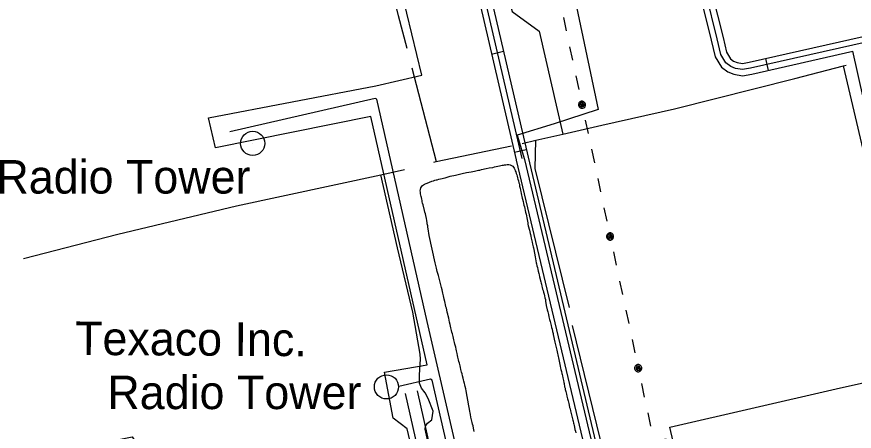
# Model space of a CAD drawing. Extents: x 3392644 to 3430565, y 576657 to 602123.
# Drawn here: x 3418875 to 3420949, y 586945 to 587973 of the extents above; entities that cross this region are included whole.
import ezdxf

# ---------------------------------------------------------------- set-up
doc = ezdxf.new("R2010")
doc.units = 0
for name, color, linetype in [('V-BLDG-IDEN', 7, 'Continuous'), ('V-ROAD-CNTR', 7, 'Continuous'), ('V-SITE-OTLN', 7, 'Continuous'), ('V-TOPO-SHOR', 7, 'Continuous'), ('V-TOPO-TOWR', 7, 'Continuous'), ('V-TOPO-TOWR-IDEN', 7, 'Continuous'), ('V-UTIL-LINE', 7, 'Continuous')]:
    doc.layers.add(name, color=color, linetype=linetype)

msp = doc.modelspace()

# ---------------------------------------------------------------- linework, layer by layer
at = {"layer": 'V-ROAD-CNTR'}
for p, q in [((3420080.7, 587886.6), (3420051.4, 587879.8)), ((3420729.6, 587869.3), (3420736.2, 587840)), ((3420137.2, 587643.1), (3420108, 587636.3))]:
    msp.add_line(p, q, dxfattribs=at)
for points in [[(3421051.4, 588862.7), (3421240.9, 588033.6), (3421246.2, 588012.9), (3421246.1, 588006.5), (3421241.1, 587991.7), (3421237.3, 587982.5), (3421228.4, 587972.9), (3421213.1, 587965.1), (3421166, 587952.4), (3420692.6, 587845.6), (3420672.4, 587842), (3420655.1, 587845.1), (3420643.4, 587849.4), (3420631.7, 587858.5), (3420619, 587879.5), (3420609.9, 587918.2), (3420582.3, 588029.6), (3420480, 588457.4), (3420453.1, 588526.7)], [(3420473.4, 588516), (3420494.4, 588461.9), (3420596.9, 588033.2), (3420624.5, 587921.8), (3420633, 587885.2), (3420643.1, 587868.7), (3420650.8, 587862.7), (3420659.1, 587859.6), (3420672.4, 587857.2), (3420689.6, 587860.3), (3421162.4, 587966.9), (3421207.7, 587979.2), (3421219.2, 587985.1), (3421224.5, 587990.7), (3421227, 587997), (3421231.1, 588009.1), (3421231.2, 588011.2), (3421226.4, 588030.1), (3421040, 588845.6)], [(3420443.8, 588509.3), (3420465.7, 588452.9), (3420567.8, 588026.1), (3420595.3, 587914.7), (3420604.9, 587873.7), (3420620.3, 587848.4), (3420636, 587836.1), (3420651.2, 587830.6), (3420672.4, 587826.7), (3420695.6, 587830.8), (3420945.6, 587887.3)], [(3420126.9, 587621.2), (3419969.1, 588300.7), (3419969, 588329.7), (3419970.4, 588348.5), (3419984.9, 588420.6)], [(3419965.6, 588400.8), (3419955.5, 588350.6), (3419954, 588330.2), (3419954.1, 588299), (3420112.3, 587617.8)], [(3419997.7, 588408.1), (3419985.3, 588346.5), (3419984, 588329.2), (3419984.1, 588302.5), (3420141.5, 587624.6)], [(3421114.8, 587130.3), (3420945.6, 587887.3)], [(3420141.5, 587624.6), (3420305.5, 586932.7), (3420314.8, 586891.6)], [(3420112.3, 587617.7), (3420276.3, 586925.9), (3420362.9, 586544), (3420374.6, 586499.3)], [(3419866.9, 587045.2), (3419967.6, 586597), (3419970.7, 586573.9), (3419960.1, 586554.5), (3419941.9, 586542.5), (3419922, 586537.6), (3419898.8, 586539.5), (3419878.4, 586544.6), (3419812.2, 586592)], [(3419837.6, 587038.6), (3419925, 586650.1)]]:
    msp.add_lwpolyline(points, dxfattribs=at)
at = {"layer": 'V-SITE-OTLN'}
for points in [[(3420198.5, 588296.2), (3420315.3, 587742.8), (3420206.2, 587707.1), (3420114.8, 587679.6), (3420133.1, 587619.1), (3420308.5, 586877.4), (3420348.3, 586694.8), (3420544.7, 586731.4), (3420492.6, 586955.3), (3420905, 587050.2), (3421093.6, 587092.6)], [(3418830.7, 586373.5), (3419131.5, 586431.4), (3419137.7, 586454.6), (3419125.3, 586527.4), (3419063.2, 586911.5), (3419161.3, 586931.7), (3419171.3, 586916.3), (3419172.8, 586898.4), (3419244.6, 586498.5), (3419674.8, 586581.6), (3419894.5, 586635.1), (3419902.8, 586662.5), (3419897.6, 586716.1), (3419842, 586951.5), (3419807.5, 586977.5), (3419785.8, 587091.7), (3419891.9, 587110), (3419751.8, 587726), (3419367.2, 587647.7), (3419349.9, 587722.2), (3419764.5, 587802.1), (3419878.1, 587827.9), (3419791.9, 588187.7)]]:
    msp.add_lwpolyline(points, dxfattribs=at)
at = {"layer": 'V-TOPO-SHOR'}
for p, q in [((3421096.6, 587108.6), (3420922.7, 587851)), ((3419853.7, 587846.4), (3419914.4, 587614.1))]:
    msp.add_line(p, q, dxfattribs=at)
for points in [[(3420058.1, 588398.7), (3420027.1, 588390), (3420020.8, 588380.5), (3420010.2, 588349.6), (3420061, 588146.3), (3420102, 587986.4), (3420168.9, 587937.5), (3420228.1, 587682.1)], [(3419792.8, 588085.1), (3419819.9, 587976.2), (3419841.1, 587894.9)], [(3420126.8, 587659.1), (3420161.1, 587666.9), (3420228.1, 587682.1), (3420324.1, 587703.8), (3420504.4, 587745), (3420801.9, 587819.7), (3420922.7, 587851), (3420929.5, 587852.8)], [(3420244.6, 587252.2), (3420158.9, 587597), (3420161.1, 587666.9)], [(3419908.1, 587612.8), (3419914.4, 587614.1), (3420100.4, 587653.3)], [(3419881.4, 587506.6), (3419880.5, 587510.5), (3419879.6, 587514.1), (3419879.1, 587517.4), (3419878.4, 587520.6), (3419877.3, 587524.5), (3419876.6, 587527.7), (3419876.3, 587530.9), (3419875.6, 587534.2), (3419874.8, 587537.9), (3419874.7, 587541.3), (3419875.1, 587544.9), (3419876.1, 587548.5), (3419877.7, 587551.2), (3419880.2, 587554.2), (3419882.6, 587556.1), (3419885.3, 587557.8), (3419889, 587559.6), (3419892.1, 587560.7), (3419903.2, 587565.1), (3419907.1, 587566.5), (3419910.7, 587567.4), (3419913.6, 587568.3), (3419916.8, 587569), (3419920.3, 587569.9), (3419924.4, 587571), (3419928.5, 587572.1), (3419931.9, 587572.8), (3419936, 587573.9), (3419939, 587574.8), (3419943.8, 587576), (3419948.6, 587577.3), (3419952.9, 587578.4), (3419957.6, 587579.5), (3419961.7, 587580.5), (3419982, 587584.9), (3419986.1, 587585.6), (3419989.1, 587586.5), (3420000.5, 587588.3), (3420004.4, 587589), (3420008.9, 587589.9), (3420018.5, 587592.2), (3420021.9, 587592.9), (3420026, 587594), (3420030.1, 587595.1), (3420033.8, 587596), (3420037.9, 587596.8), (3420045.6, 587598), (3420054, 587599.5), (3420058.2, 587600.6), (3420062.5, 587601.5), (3420070.6, 587603), (3420074.3, 587603.9), (3420077.6, 587604.6), (3420080.6, 587605.1), (3420083.6, 587605.8), (3420086.8, 587606.1), (3420090.2, 587606.4), (3420093.9, 587606.4), (3420097.3, 587605.6), (3420100.6, 587603.8), (3420103.5, 587602.3), (3420105.9, 587599.7), (3420107.5, 587597.2), (3420108.7, 587594), (3420109.8, 587590.9), (3420111, 587588.1), (3420112.3, 587584.4), (3420113.4, 587580.9), (3420114.3, 587577.7), (3420115.4, 587573.8), (3420116.5, 587570.5), (3420118, 587565.8), (3420119.1, 587561), (3420120, 587558), (3420120.7, 587553.3), (3420122.1, 587548.1), (3420123, 587543.3), (3420123.8, 587539.5), (3420124.9, 587534.7), (3420127.1, 587523.5), (3420127.7, 587520.5), (3420129.1, 587515.3), (3420130.2, 587510.3), (3420131.2, 587506), (3420132.5, 587501.4)], [(3418891.8, 587373.6), (3419125.2, 587434), (3419419.8, 587504.4), (3419776.7, 587581.4), (3419835.9, 587594.1)], [(3419918.1, 586808.2), (3419887, 586950.7), (3419887.4, 586958), (3419892.4, 586965.5), (3419903.3, 586973.3), (3419906.4, 586994.6), (3419893.8, 587026.6), (3419886.6, 587040.8), (3419877.5, 587052.4), (3419872.4, 587064.8), (3419872.6, 587074.7), (3419872.9, 587085.3), (3419875.2, 587123.9), (3419874.1, 587136.4), (3419855.9, 587240.4), (3419818.1, 587399.9), (3419776.7, 587581.4)], [(3419957.9, 587172), (3419957, 587176.1), (3419955.9, 587180.4), (3419954.4, 587186.6), (3419953.1, 587191.1), (3419952.3, 587195.1), (3419950.7, 587201.3), (3419949.8, 587205.5), (3419948.8, 587209.5), (3419947.2, 587215.9), (3419946.1, 587220.7), (3419945.1, 587225.2), (3419943.5, 587231.6), (3419942.6, 587235.8), (3419941.5, 587240.3), (3419940.1, 587246.2), (3419939.2, 587250.4), (3419938.3, 587254.1), (3419936.9, 587259.2), (3419936.2, 587263.1), (3419935.3, 587266.9), (3419933.9, 587272.7), (3419933, 587276.7), (3419932.1, 587281), (3419930.6, 587287.5), (3419929.7, 587291.6), (3419928.9, 587295.5), (3419927.4, 587301.5), (3419924.3, 587315), (3419923.4, 587318), (3419921.3, 587324.8), (3419919.4, 587331.1), (3419917.8, 587336.7), (3419916.5, 587341.5), (3419915.6, 587345.5), (3419914.6, 587349.7), (3419913.1, 587356), (3419912, 587359.8), (3419911.3, 587363), (3419896.8, 587430.2), (3419894.2, 587447.4), (3419893.5, 587450.9), (3419893, 587454.3), (3419892, 587459.3), (3419891.7, 587462.3), (3419890.5, 587467.9), (3419889.8, 587472.6), (3419888.1, 587480.4), (3419887.2, 587484.7), (3419885.9, 587488.6), (3419884.8, 587492.7), (3419881.4, 587506.6)], [(3420132.5, 587501.4), (3420133.4, 587497.6), (3420134.5, 587492.6), (3420135.5, 587488.5), (3420136.6, 587483.7), (3420137.7, 587479.2), (3420138.7, 587474.3), (3420140.9, 587462), (3420141.4, 587458.7), (3420141.9, 587454.5), (3420145, 587443.8), (3420146.3, 587439.7), (3420147.2, 587435.8), (3420147.7, 587432.8), (3420148.6, 587428.7), (3420149.4, 587424), (3420150.3, 587420.7), (3420151, 587417.5), (3420151.9, 587413.8), (3420152.6, 587409.3), (3420153.5, 587405.7), (3420154.2, 587402.6), (3420155.3, 587399.6), (3420156.2, 587395.5), (3420159.6, 587377.6), (3420162, 587363.2), (3420162.7, 587360), (3420163.6, 587355.5), (3420164.7, 587351.1), (3420166.1, 587346.4), (3420167, 587342.1), (3420168.3, 587336.6), (3420169.1, 587332.8), (3420170.2, 587328.2), (3420173.2, 587315.5), (3420173.8, 587312.5), (3420174.7, 587309.5), (3420175.8, 587305.1), (3420176.5, 587301.9), (3420177.7, 587297.4), (3420178.7, 587294.3), (3420179.8, 587290.4), (3420181.2, 587285), (3420182.3, 587280.9), (3420183.4, 587275.7), (3420184.4, 587272), (3420185.1, 587266.9), (3420185.8, 587263), (3420186.7, 587257.2), (3420189.2, 587246.4), (3420190.3, 587241.5), (3420191.2, 587237.8), (3420192.1, 587234.3), (3420193.3, 587229.3), (3420194.2, 587225.7), (3420195, 587222.6), (3420196.2, 587217.3), (3420196.9, 587214.4), (3420198.7, 587207.5), (3420200, 587202.3), (3420200.9, 587198), (3420202.5, 587192.4), (3420203.4, 587187.9), (3420204.1, 587184.8), (3420207.5, 587165.9), (3420212.5, 587146.4), (3420213.4, 587142.3), (3420214.3, 587137.6), (3420215.2, 587134.4), (3420216.3, 587130.3), (3420217, 587127.2), (3420218.1, 587122.9), (3420221.1, 587106.3), (3420222, 587101.6), (3420222.7, 587098.1), (3420224.1, 587093.4)], [(3420483.3, 586925.5), (3420345.4, 586896), (3420336, 586898.2), (3420321.9, 586920.2), (3420251.8, 587207.4)], [(3420008.4, 586944.8), (3420007.5, 586948.5), (3420006.8, 586952.7), (3420005.3, 586958.4), (3420003.9, 586962.9), (3420003.2, 586967), (3420001.4, 586973.3), (3420000.5, 586977.2), (3419999.8, 586980.2), (3419998.7, 586986.4), (3419997.9, 586990.5), (3419997.4, 586994.4), (3419996.2, 587000), (3419995.5, 587004.3), (3419994.9, 587008.4), (3419988.1, 587045.7), (3419987.2, 587050), (3419985.8, 587056.2), (3419984.9, 587060.1), (3419984, 587064), (3419982.6, 587069.4), (3419981.7, 587073.1), (3419980.8, 587076.8), (3419979.4, 587083), (3419978.1, 587087.4), (3419977, 587091.7), (3419975.2, 587098.4), (3419974.1, 587103.1), (3419973.2, 587107.2), (3419971.4, 587114.2), (3419970.5, 587118.3), (3419969.5, 587122.6), (3419968, 587129), (3419966.8, 587133.4), (3419965.9, 587137.7), (3419964.3, 587144.4), (3419963.4, 587148.5), (3419962.6, 587153.4), (3419960.6, 587160.8), (3419959.7, 587165.1), (3419957.9, 587172)], [(3420224.1, 587093.4), (3420225, 587088.8), (3420225.9, 587085.8), (3420226.8, 587082.4), (3420227.7, 587077.6), (3420228.4, 587074.4), (3420229.3, 587071.1), (3420230.1, 587066.4), (3420230.7, 587063.2), (3420232.2, 587055.6), (3420233.1, 587052.4), (3420233.8, 587048.9), (3420235.1, 587043.7), (3420236, 587040.3), (3420236.7, 587037), (3420237.8, 587032.5), (3420238.7, 587029.2), (3420239.4, 587025.8), (3420240.8, 587020.6), (3420241.7, 587017.2), (3420242.4, 587014.3), (3420243.5, 587009.8), (3420244.6, 587004.4), (3420245.7, 587000.9), (3420246.7, 586995.8), (3420247.6, 586992.1), (3420249.2, 586986), (3420249.8, 586983), (3420251.7, 586975.7), (3420252.5, 586972.7), (3420253.2, 586969.8), (3420254.3, 586965.5), (3420255, 586962.5), (3420255.7, 586959.5), (3420256.6, 586955.2), (3420257.8, 586949.6), (3420259.1, 586945.2), (3420259.8, 586941.6)]]:
    msp.add_lwpolyline(points, dxfattribs=at)
at = {"layer": 'V-TOPO-TOWR'}
for p, q in [((3419459.7, 587658.9), (3419459.7, 587658.9)), ((3419790.9, 587055.2), (3419790.9, 587055.2))]:
    msp.add_line(p, q, dxfattribs=at)
for centre in [(3419459.7, 587658.9), (3419790.9, 587055.2)]:
    msp.add_circle(centre, 30, dxfattribs=at)
at = {"layer": 'V-UTIL-LINE'}
for points in [[(3420229.1, 587971), (3420236.2, 587937.7)], [(3420244.6, 587898.6), (3420251.6, 587865.4)], [(3420260, 587826.2), (3420267.1, 587793)], [(3420082.2, 586296.2), (3420108.5, 586299.9), (3420031, 586622.1), (3420049.9, 586627.6), (3420041.3, 586661.7), (3420020.9, 586657.5), (3420019.3, 586662.8), (3419891.4, 587217.4), (3419766.9, 587768.6), (3419762.8, 587770.5), (3419403.3, 587687.4)], [(3420275.2, 587754.8), (3420277.2, 587756.9), (3420274.8, 587757.3), (3420273, 587755.2), (3420273.9, 587752.4), (3420277.3, 587753), (3420279.9, 587756.9), (3420277.4, 587760.3), (3420272.5, 587760.6), (3420269.9, 587756.9), (3420269.8, 587752.4), (3420273.6, 587749.4), (3420279, 587750.2), (3420284, 587756.7), (3420282.6, 587759.9), (3420280.1, 587762.4), (3420276.8, 587763.7), (3420273.3, 587763.6), (3420270.1, 587762.2), (3420267.6, 587759.7), (3420266.3, 587756.5), (3420266.4, 587753), (3420267.8, 587749.7), (3420270.3, 587747.3), (3420273.5, 587746), (3420277.1, 587746), (3420280.3, 587747.4), (3420282.7, 587749.9), (3420284, 587753.2), (3420284, 587756.7)], [(3420283.3, 587716.7), (3420290.4, 587683.4)], [(3420298.7, 587644.3), (3420305.8, 587611.1)], [(3420314.1, 587571.9), (3420321.2, 587538.7)], [(3420329.5, 587499.6), (3420336.6, 587466.3)], [(3420344.7, 587428.2), (3420346.7, 587430.2), (3420344.4, 587430.6), (3420342.6, 587428.5), (3420343.5, 587425.8), (3420346.9, 587426.3), (3420349.5, 587430.2), (3420347, 587433.6), (3420342.1, 587433.9), (3420339.4, 587430.2), (3420339.4, 587425.7), (3420343.2, 587422.7), (3420348.6, 587423.5), (3420353.6, 587430), (3420352.2, 587433.3), (3420349.6, 587435.7), (3420346.4, 587437), (3420342.9, 587437), (3420339.6, 587435.6), (3420337.2, 587433.1), (3420335.9, 587429.8), (3420335.9, 587426.3), (3420337.3, 587423.1), (3420339.8, 587420.6), (3420343.1, 587419.3), (3420346.6, 587419.4), (3420349.8, 587420.7), (3420352.3, 587423.3), (3420353.6, 587426.5), (3420353.6, 587430)], [(3420352.9, 587390), (3420360, 587356.8)], [(3420368.3, 587317.6), (3420375.4, 587284.4)], [(3420383.7, 587245.3), (3420390.8, 587212)], [(3420399.1, 587172.9), (3420406.2, 587139.6)], [(3420414.3, 587101.5), (3420416.3, 587103.6), (3420414, 587103.9), (3420412.2, 587101.9), (3420413.1, 587099.1), (3420416.4, 587099.6), (3420419.1, 587103.5), (3420416.5, 587106.9), (3420411.7, 587107.2), (3420409, 587103.5), (3420409, 587099), (3420412.7, 587096), (3420418.2, 587096.9), (3420423.1, 587103.4), (3420421.7, 587106.6), (3420419.2, 587109), (3420416, 587110.3), (3420412.4, 587110.3), (3420409.2, 587108.9), (3420406.8, 587106.4), (3420405.5, 587103.1), (3420405.5, 587099.6), (3420406.9, 587096.4), (3420409.4, 587093.9), (3420412.7, 587092.6), (3420416.2, 587092.7), (3420419.4, 587094.1), (3420421.9, 587096.6), (3420423.2, 587099.8), (3420423.1, 587103.4)], [(3420082.2, 586296.2), (3420011.1, 586604.1), (3420009.1, 586606.7), (3419984.1, 586601), (3419978.5, 586624.6), (3420002.1, 586629.6), (3420003.9, 586635), (3419904.4, 587071.6), (3419899.7, 587074.1), (3419821.9, 587056.4)], [(3420422.4, 587063.3), (3420429.5, 587030.1)], [(3420437.9, 586991), (3420444.9, 586957.7)]]:
    msp.add_lwpolyline(points, dxfattribs=at)

# ---------------------------------------------------------------- texts
at = {"layer": 'V-BLDG-IDEN'}
msp.add_text('Texaco Inc.', height=83, rotation=359.6858, dxfattribs=at).set_placement((3419019.6, 587134.4))
at = {"layer": 'V-TOPO-TOWR-IDEN'}
for p in [(3418824.9, 587534.6), (3419099.7, 587000.1)]:
    msp.add_text('Radio Tower', height=83, dxfattribs=at).set_placement(p)

doc.saveas('drawing.dxf')
